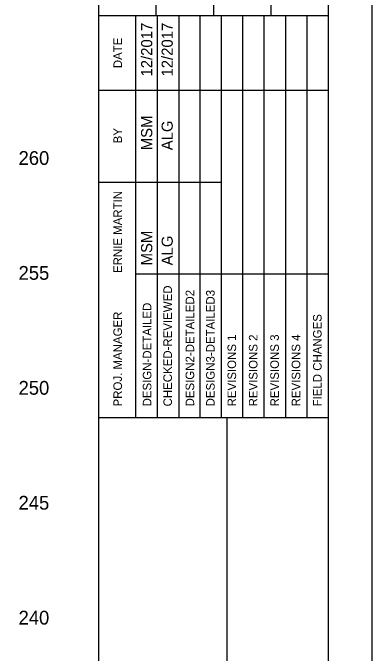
# Model space of a CAD drawing. Extents: x 859352 to 859522, y 366268 to 366378.
# Drawn here: x 859506.38 to 859522.04, y 366305.99 to 366333.85 of the extents above; entities that cross this region are included whole.
import ezdxf

# ---------------------------------------------------------------- set-up
doc = ezdxf.new("R2010")
doc.units = 0
for name, color, linetype in [('BORDER', 7, 'Continuous'), ('H_V ANNOTATION', 7, 'Continuous'), ('PLOT BOUNDARY', 7, 'Continuous')]:
    doc.layers.add(name, color=color, linetype=linetype)

msp = doc.modelspace()

# ---------------------------------------------------------------- linework, layer by layer
at = {"layer": 'BORDER'}
for p, q in [((859510.13, 366271.236), (859510.13, 366376.239)), ((859520.13, 366271.236), (859520.13, 366376.236)), ((859512.63, 366333.739), (859512.63, 366342.387)), ((859515.13, 366333.739), (859515.13, 366342.387)), ((859517.63, 366333.739), (859517.63, 366342.387)), ((859510.13, 366333.739), (859520.13, 366333.739)), ((859510.13, 366316.239), (859520.13, 366316.239)), ((859515.721, 366281.239), (859515.721, 366316.239))]:
    msp.add_line(p, q, dxfattribs=at)
for points in [[(859511.744, 366330.489), (859511.744, 366333.739)], [(859512.677, 366316.242), (859512.677, 366333.739)], [(859513.609, 366333.739), (859513.609, 366316.242)], [(859514.54, 366316.242), (859514.54, 366333.739)], [(859515.472, 366316.242), (859515.472, 366333.739)], [(859516.404, 366316.242), (859516.404, 366333.739)], [(859517.335, 366316.242), (859517.335, 366333.739)], [(859518.267, 366316.242), (859518.267, 366333.739)], [(859519.199, 366316.242), (859519.199, 366333.739)], [(859511.745, 366316.242), (859511.745, 366333.033)], [(859510.13, 366330.489), (859520.13, 366330.489)], [(859510.13, 366326.489), (859511.745, 366326.489)], [(859511.744, 366326.489), (859515.471, 366326.489)], [(859511.744, 366322.489), (859520.13, 366322.489)]]:
    msp.add_lwpolyline(points, dxfattribs=at)
at = {"layer": 'PLOT BOUNDARY'}
msp.add_lwpolyline([(859352.036, 366268.177), (859522.036, 366268.177), (859522.036, 366378.177), (859352.036, 366378.177)], close=True, dxfattribs=at)

# ---------------------------------------------------------------- texts
at = {"layer": 'BORDER'}
for s, height, p in [('12/2017', 0.4845, (859512.453, 366331.081)), ('12/2017', 0.4845, (859513.347, 366331.081)), ('DATE', 0.3714, (859511.134, 366331.445)), ('MSM', 0.4845, (859512.453, 366327.872)), ('ALG', 0.4845, (859513.347, 366327.872)), ('BY', 0.3714, (859511.134, 366328.174)), ('ERNIE MARTIN', 0.37275, (859511.134, 366322.531)), ('MSM', 0.4845, (859512.453, 366322.863)), ('ALG', 0.4845, (859513.347, 366322.863)), ('CHECKED-REVIEWED', 0.37275, (859513.311, 366316.727)), ('DESIGN2-DETAILED2', 0.37275, (859514.28, 366316.727)), ('DESIGN3-DETAILED3', 0.37275, (859515.174, 366316.727)), ('DESIGN-DETAILED', 0.37275, (859512.416, 366316.727)), ('PROJ. MANAGER', 0.37275, (859511.134, 366316.727)), ('FIELD CHANGES', 0.37275, (859519.832, 366316.727)), ('REVISIONS 1', 0.37275, (859516.106, 366316.727)), ('REVISIONS 2', 0.37275, (859517.037, 366316.727)), ('REVISIONS 3', 0.37275, (859517.969, 366316.727)), ('REVISIONS 4', 0.37275, (859518.901, 366316.727))]:
    msp.add_text(s, height=height, rotation=90, dxfattribs=at).set_placement(p)
at = {"layer": 'H_V ANNOTATION'}
for s, p in [('260', (859506.629, 366327.236)), ('255', (859506.629, 366322.236)), ('250', (859506.629, 366317.236)), ('245', (859506.629, 366312.236)), ('240', (859506.629, 366307.236))]:
    msp.add_text(s, height=0.6, dxfattribs=at).set_placement(p)

doc.saveas('drawing.dxf')
